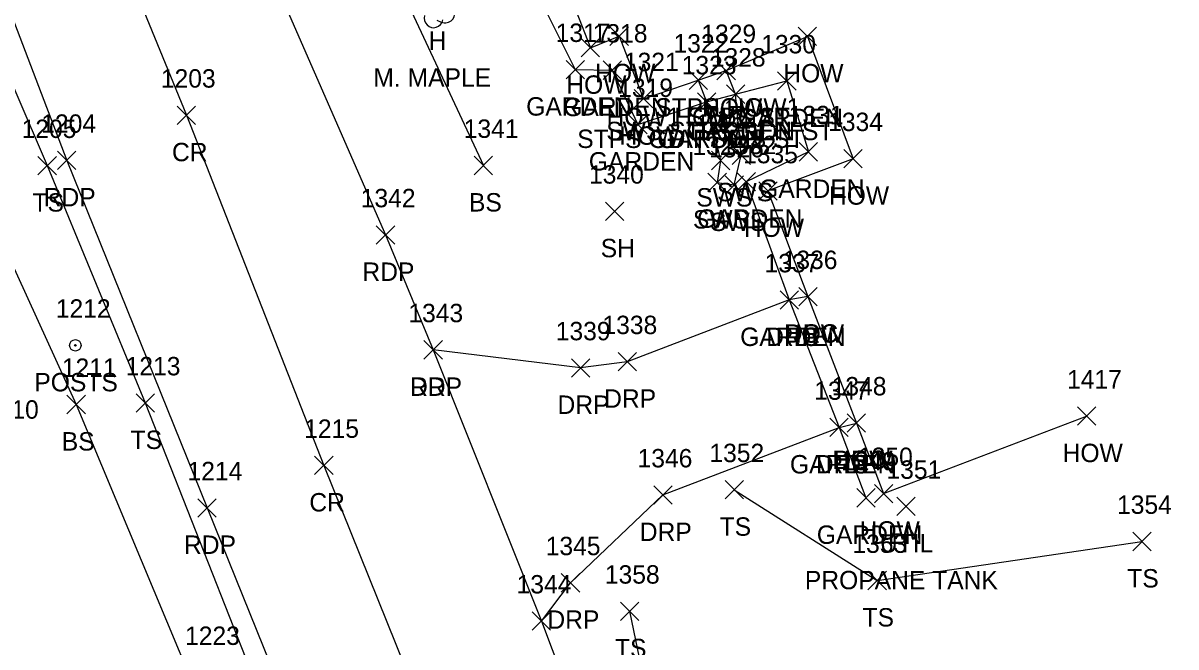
# Model space of a CAD drawing. Extents: x 1651305 to 1654558, y 539481 to 548441.
# Drawn here: x 1654203 to 1654328.2, y 544875.3 to 544943.1 of the extents above; entities that cross this region are included whole.
import ezdxf

# ---------------------------------------------------------------- set-up
doc = ezdxf.new("R2010")
doc.units = 0
for name, color, linetype in [('L_A', 7, 'Continuous'), ('L_C', 7, 'Continuous'), ('L_I', 7, 'Continuous'), ('L_TIC', 7, 'Continuous'), ('LAPB', 7, 'Continuous'), ('LBC', 7, 'Continuous'), ('LBF', 7, 'Continuous'), ('LELB', 7, 'Continuous'), ('LPST', 7, 'Continuous'), ('LTD', 7, 'Continuous'), ('P_A', 7, 'Continuous'), ('P_I', 7, 'Continuous'), ('P_TIC', 7, 'Continuous'), ('PET', 7, 'Continuous'), ('PRC', 7, 'Continuous'), ('R_A', 7, 'Continuous'), ('R_I', 7, 'Continuous'), ('R_TIC', 7, 'Continuous'), ('RDP', 7, 'Continuous'), ('RSW', 7, 'Continuous'), ('S_I', 7, 'Continuous'), ('U_A', 7, 'Continuous'), ('U_C', 7, 'Continuous'), ('U_I', 7, 'Continuous'), ('UDEFAULT', 7, 'Continuous')]:
    doc.layers.add(name, color=color, linetype=linetype)

msp = doc.modelspace()

# ---------------------------------------------------------------- linework, layer by layer
at = {"layer": 'L_TIC'}
for points in [[(1654266.72, 544940.66), (1654268.72, 544942.66)], [(1654268.72, 544940.66), (1654266.72, 544942.66)], [(1654287.15, 544940.64), (1654289.15, 544942.64)], [(1654289.15, 544940.64), (1654287.15, 544942.64)], [(1654263.6, 544939.4), (1654265.6, 544941.4)], [(1654265.6, 544939.4), (1654263.6, 544941.4)], [(1654261.96, 544937.03), (1654263.96, 544939.03)], [(1654263.96, 544937.03), (1654261.96, 544939.03)], [(1654265.98, 544936.97), (1654267.98, 544938.97)], [(1654267.98, 544936.97), (1654265.98, 544938.97)], [(1654278.34, 544936.92), (1654280.34, 544938.92)], [(1654280.34, 544936.92), (1654278.34, 544938.92)], [(1654278.34, 544936.92), (1654280.34, 544938.92)], [(1654280.34, 544936.92), (1654278.34, 544938.92)], [(1654275.31, 544935.88), (1654277.31, 544937.88)], [(1654277.31, 544935.88), (1654275.31, 544937.88)], [(1654275.31, 544935.88), (1654277.31, 544937.88)], [(1654277.31, 544935.88), (1654275.31, 544937.88)], [(1654284.92, 544935.79), (1654286.92, 544937.79)], [(1654286.92, 544935.79), (1654284.92, 544937.79)], [(1654279.36, 544934.36), (1654281.36, 544936.36)], [(1654281.36, 544934.36), (1654279.36, 544936.36)], [(1654279.36, 544934.36), (1654281.36, 544936.36)], [(1654281.36, 544934.36), (1654279.36, 544936.36)], [(1654269.37, 544933.86), (1654271.37, 544935.86)], [(1654271.37, 544933.86), (1654269.37, 544935.86)], [(1654276.21, 544933.51), (1654278.21, 544935.51)], [(1654278.21, 544933.51), (1654276.21, 544935.51)], [(1654276.21, 544933.51), (1654278.21, 544935.51)], [(1654278.21, 544933.51), (1654276.21, 544935.51)], [(1654268.76, 544931.06), (1654270.76, 544933.06)], [(1654270.76, 544931.06), (1654268.76, 544933.06)], [(1654287.26, 544928.09), (1654289.26, 544930.09)], [(1654289.26, 544928.09), (1654287.26, 544930.09)], [(1654204.63, 544926.6), (1654206.63, 544928.6)], [(1654206.63, 544926.6), (1654204.63, 544928.6)], [(1654251.98, 544926.61), (1654253.98, 544928.61)], [(1654253.98, 544926.61), (1654251.98, 544928.61)], [(1654292.11, 544927.35), (1654294.11, 544929.35)], [(1654294.11, 544927.35), (1654292.11, 544929.35)], [(1654280.51, 544924.84), (1654282.51, 544926.84)], [(1654282.51, 544924.84), (1654280.51, 544926.84)], [(1654282.87, 544923.85), (1654284.87, 544925.85)], [(1654284.87, 544923.85), (1654282.87, 544925.85)], [(1654266.23, 544921.64), (1654268.23, 544923.64)], [(1654268.23, 544921.64), (1654266.23, 544923.64)], [(1654285.19, 544912), (1654287.19, 544914)], [(1654287.19, 544912), (1654285.19, 544914)], [(1654287.22, 544912.36), (1654289.22, 544914.36)], [(1654289.22, 544912.36), (1654287.22, 544914.36)], [(1654207.78, 544900.64), (1654209.78, 544902.64)], [(1654209.78, 544900.64), (1654207.78, 544902.64)], [(1654215.28, 544900.81), (1654217.28, 544902.81)], [(1654217.28, 544900.81), (1654215.28, 544902.81)], [(1654317.47, 544899.38), (1654319.47, 544901.38)], [(1654319.47, 544899.38), (1654317.47, 544901.38)], [(1654290.59, 544898.15), (1654292.59, 544900.15)], [(1654292.59, 544898.15), (1654290.59, 544900.15)], [(1654292.48, 544898.63), (1654294.48, 544900.63)], [(1654294.48, 544898.63), (1654292.48, 544900.63)], [(1654279.22, 544891.38), (1654281.22, 544893.38)], [(1654281.22, 544891.38), (1654279.22, 544893.38)], [(1654293.51, 544890.5), (1654295.51, 544892.5)], [(1654295.51, 544890.5), (1654293.51, 544892.5)], [(1654295.43, 544890.96), (1654297.43, 544892.96)], [(1654297.43, 544890.96), (1654295.43, 544892.96)], [(1654323.47, 544885.76), (1654325.47, 544887.76)], [(1654325.47, 544885.76), (1654323.47, 544887.76)], [(1654294.73, 544881.52), (1654296.73, 544883.52)], [(1654296.73, 544881.52), (1654294.73, 544883.52)], [(1654267.86, 544878.18), (1654269.86, 544880.18)], [(1654269.86, 544878.18), (1654267.86, 544880.18)]]:
    msp.add_lwpolyline(points, dxfattribs=at)
at = {"layer": 'LAPB'}
for points in [[(1654256.41, 544951.2), (1654262.96, 544938.03), (1654266.98, 544937.97), (1654269.76, 544932.06), (1654277.21, 544934.51)], [(1654280.36, 544935.36), (1654285.92, 544936.79), (1654288.26, 544929.09), (1654281.51, 544925.84), (1654286.19, 544913)], [(1654291.59, 544899.15), (1654294.51, 544891.5)]]:
    msp.add_lwpolyline(points, dxfattribs=at)
at = {"layer": 'LBC'}
msp.add_lwpolyline([(1654281.63, 544981.34), (1654252.91, 544971.12), (1654257.65, 544958.01), (1654259.95, 544952.38), (1654264.6, 544940.4), (1654267.72, 544941.66), (1654270.37, 544934.86), (1654276.31, 544936.88), (1654279.34, 544937.92), (1654288.15, 544941.64), (1654293.11, 544928.35), (1654283.87, 544924.85), (1654288.22, 544913.36), (1654293.48, 544899.63), (1654296.43, 544891.96), (1654318.47, 544900.38)], dxfattribs=at)
at = {"layer": 'LBF'}
msp.add_lwpolyline([(1654276.31, 544936.88), (1654277.21, 544934.51), (1654280.36, 544935.36), (1654279.34, 544937.92)], dxfattribs=at)
at = {"layer": 'LELB'}
for points in [[(1654179.72, 544986.88), (1654191.76, 544959.88), (1654205.63, 544927.6), (1654216.28, 544901.81), (1654236.78, 544849.69), (1654250.25, 544817.94), (1654269.19, 544772.35), (1654285.71, 544732), (1654294.18, 544708.03), (1654311.84, 544664.34)], [(1654177.71, 544985.41), (1654186.4, 544960.29), (1654198.08, 544925.07), (1654208.78, 544901.64), (1654231.34, 544847.61), (1654245.85, 544816.46), (1654261.74, 544769.7), (1654274.87, 544730.83), (1654284.44, 544695.19), (1654297.61, 544656.98), (1654309.41, 544642.27)], [(1654232.47, 544981.12), (1654243.09, 544948.86), (1654252.98, 544927.61)], [(1654280.22, 544892.38), (1654295.73, 544882.52), (1654324.47, 544886.76)], [(1654268.86, 544879.18), (1654276.49, 544842.28), (1654286.12, 544815.62), (1654299.15, 544783.59), (1654310.71, 544759.79), (1654316.89, 544741.3), (1654328.16, 544712.61)]]:
    msp.add_lwpolyline(points, dxfattribs=at)
at = {"layer": 'LPST'}
for radius in [0.625, 0.0833]:
    msp.add_circle((1654208.69, 544908.07), radius, dxfattribs=at)
at = {"layer": 'LTD'}
for centre, major_axis, ratio in [((1654248.6, 544944.33), (-1.09, 0.79), 0.841452), ((1654247.6, 544943.67), (0.26, 1.06), 0.942809)]:
    msp.add_ellipse(centre, major_axis=major_axis, ratio=ratio, start_param=1.570796, end_param=4.712389, dxfattribs=at)
at = {"layer": 'P_TIC'}
for points in [[(1654219.75, 544932.07), (1654221.75, 544934.07)], [(1654221.75, 544932.07), (1654219.75, 544934.07)], [(1654206.76, 544927.16), (1654208.76, 544929.16)], [(1654208.76, 544927.16), (1654206.76, 544929.16)], [(1654241.36, 544919.07), (1654243.36, 544921.07)], [(1654243.36, 544919.07), (1654241.36, 544921.07)], [(1654246.53, 544906.58), (1654248.53, 544908.58)], [(1654248.53, 544906.58), (1654246.53, 544908.58)], [(1654234.66, 544894.02), (1654236.66, 544896.02)], [(1654236.66, 544894.02), (1654234.66, 544896.02)], [(1654221.99, 544889.41), (1654223.99, 544891.41)], [(1654223.99, 544889.41), (1654221.99, 544891.41)], [(1654258.28, 544877.11), (1654260.28, 544879.11)], [(1654260.28, 544877.11), (1654258.28, 544879.11)]]:
    msp.add_lwpolyline(points, dxfattribs=at)
at = {"layer": 'PET'}
for points in [[(1654139.13, 545176.5), (1654150.39, 545147.19), (1654157.16, 545131.71), (1654170.76, 545099.13), (1654178.15, 545080.65), (1654186.44, 545060.96), (1654201.83, 545022.37), (1654207.18, 545004.72), (1654219.14, 544973.24), (1654242.36, 544920.07), (1654247.53, 544907.58), (1654259.28, 544878.11), (1654268.46, 544853.76), (1654271.52, 544840.23), (1654282.76, 544813.43), (1654295.45, 544782.26), (1654306.75, 544753.72), (1654320.35, 544717.46), (1654325.71, 544702.64)], [(1654112.87, 545166.54), (1654122.04, 545140.21), (1654132.62, 545111.94), (1654135.36, 545108.19), (1654138.44, 545103.48), (1654151.39, 545069.68), (1654150.58, 545065.43), (1654160.56, 545041.12), (1654174.1, 545006.91), (1654181.29, 544989.93), (1654184.89, 544987.01), (1654195.03, 544961.54), (1654207.76, 544928.16), (1654222.99, 544890.41), (1654239.03, 544850.69), (1654252.07, 544818.68), (1654270.72, 544773.03), (1654287.36, 544732.43), (1654297.76, 544708.46), (1654313.88, 544667.1), (1654319.77, 544684.6), (1654325.71, 544702.64)]]:
    msp.add_lwpolyline(points, dxfattribs=at)
at = {"layer": 'PRC'}
msp.add_lwpolyline([(1654126.32, 545171.74), (1654141.33, 545133.41), (1654151.93, 545107.49), (1654165.21, 545072.69), (1654175.57, 545046.61), (1654188.97, 545011.94), (1654198.02, 544989.46), (1654207.45, 544965.61), (1654220.75, 544933.07), (1654235.66, 544895.02), (1654251.31, 544856.19), (1654265.06, 544822.16), (1654283.02, 544778.21), (1654298.76, 544737.49), (1654308.6, 544712.81), (1654319.77, 544684.6)], dxfattribs=at)
at = {"layer": 'R_TIC'}
for points in [[(1654279.36, 544934.36), (1654281.36, 544936.36)], [(1654281.36, 544934.36), (1654279.36, 544936.36)], [(1654276.21, 544933.51), (1654278.21, 544935.51)], [(1654278.21, 544933.51), (1654276.21, 544935.51)], [(1654277.73, 544927.15), (1654279.73, 544929.15)], [(1654279.73, 544927.15), (1654277.73, 544929.15)], [(1654279.98, 544927.72), (1654281.98, 544929.72)], [(1654281.98, 544927.72), (1654279.98, 544929.72)], [(1654277.36, 544924.76), (1654279.36, 544926.76)], [(1654279.36, 544924.76), (1654277.36, 544926.76)], [(1654279.22, 544924.49), (1654281.22, 544926.49)], [(1654281.22, 544924.49), (1654279.22, 544926.49)], [(1654285.19, 544912), (1654287.19, 544914)], [(1654287.19, 544912), (1654285.19, 544914)], [(1654285.19, 544912), (1654287.19, 544914)], [(1654287.19, 544912), (1654285.19, 544914)], [(1654287.22, 544912.36), (1654289.22, 544914.36)], [(1654289.22, 544912.36), (1654287.22, 544914.36)], [(1654246.53, 544906.58), (1654248.53, 544908.58)], [(1654248.53, 544906.58), (1654246.53, 544908.58)], [(1654267.6, 544905.29), (1654269.6, 544907.29)], [(1654269.6, 544905.29), (1654267.6, 544907.29)], [(1654262.54, 544904.62), (1654264.54, 544906.62)], [(1654264.54, 544904.62), (1654262.54, 544906.62)], [(1654290.59, 544898.15), (1654292.59, 544900.15)], [(1654292.59, 544898.15), (1654290.59, 544900.15)], [(1654290.59, 544898.15), (1654292.59, 544900.15)], [(1654292.59, 544898.15), (1654290.59, 544900.15)], [(1654292.48, 544898.63), (1654294.48, 544900.63)], [(1654294.48, 544898.63), (1654292.48, 544900.63)], [(1654271.47, 544890.81), (1654273.47, 544892.81)], [(1654273.47, 544890.81), (1654271.47, 544892.81)], [(1654261.44, 544881.27), (1654263.44, 544883.27)], [(1654263.44, 544881.27), (1654261.44, 544883.27)], [(1654258.28, 544877.11), (1654260.28, 544879.11)], [(1654260.28, 544877.11), (1654258.28, 544879.11)]]:
    msp.add_lwpolyline(points, dxfattribs=at)
at = {"layer": 'RDP'}
for points in [[(1654286.19, 544913), (1654268.6, 544906.29), (1654263.54, 544905.62), (1654247.53, 544907.58)], [(1654288.22, 544913.36), (1654286.19, 544913), (1654291.59, 544899.15), (1654293.48, 544899.63)], [(1654259.28, 544878.11), (1654262.44, 544882.27), (1654272.47, 544891.81), (1654291.59, 544899.15)]]:
    msp.add_lwpolyline(points, dxfattribs=at)
at = {"layer": 'RSW'}
msp.add_lwpolyline([(1654277.21, 544934.51), (1654278.73, 544928.15), (1654278.36, 544925.76), (1654280.22, 544925.49), (1654280.98, 544928.72), (1654280.36, 544935.36)], dxfattribs=at)
at = {"layer": 'UDEFAULT'}
for points in [[(1654297.87, 544889.57), (1654299.87, 544891.57)], [(1654299.87, 544889.57), (1654297.87, 544891.57)]]:
    msp.add_lwpolyline(points, dxfattribs=at)

# ---------------------------------------------------------------- texts
at = {"layer": 'L_A'}
for s, p in [('H', (1654247.03, 544940.17)), ('HOW', (1654265.11, 544936.66)), ('HOW', (1654285.54, 544936.64)), ('HOW', (1654261.98, 544935.4)), ('GARDEN', (1654257.63, 544933.03)), ('GARDEN', (1654261.65, 544932.97)), ('STPS HOW1', (1654271.64, 544932.92)), ('HOW', (1654276.73, 544932.92)), ('HOW1 STPS ST', (1654266.35, 544931.88)), ('HOW', (1654273.7, 544931.88)), ('GARDEN', (1654280.59, 544931.79)), ('SWS STPS GDN ST', (1654266.32, 544930.36)), ('GARDEN', (1654275.03, 544930.36)), ('STPS GDN SWS ST', (1654263.17, 544929.51)), ('HOW', (1654267.75, 544929.86)), ('GARDEN', (1654271.87, 544929.51)), ('GARDEN', (1654264.43, 544927.06)), ('GARDEN', (1654282.92, 544924.09)), ('HOW', (1654290.49, 544923.35)), ('TS', (1654204.04, 544922.6)), ('BS', (1654251.42, 544922.61)), ('GARDEN', (1654276.18, 544920.84)), ('HOW', (1654281.26, 544919.85)), ('SH', (1654265.72, 544917.64)), ('GARDEN', (1654280.86, 544908)), ('HOW', (1654285.6, 544908.36)), ('POSTS', (1654204.24, 544903.07)), ('BS', (1654207.22, 544896.64)), ('TS', (1654214.69, 544896.81)), ('HOW', (1654315.86, 544895.38)), ('GARDEN', (1654286.26, 544894.15)), ('HOW', (1654290.87, 544894.63)), ('TS', (1654278.63, 544887.38)), ('GARDEN', (1654289.18, 544886.5)), ('HOW', (1654293.82, 544886.96)), ('TS', (1654322.88, 544881.76)), ('TS', (1654294.14, 544877.52)), ('TS', (1654267.27, 544874.18))]:
    msp.add_text(s, height=2, dxfattribs=at).set_placement(p)
at = {"layer": 'L_C'}
msp.add_text('M. MAPLE', height=2, dxfattribs=at).set_placement((1654241.04, 544936.17))
at = {"layer": 'L_I'}
for s, p in [('1317', (1654260.83, 544941.03)), ('1318', (1654264.85, 544940.97)), ('1329', (1654276.64, 544940.92)), ('1329', (1654276.64, 544940.92)), ('1322', (1654273.62, 544939.88)), ('1322', (1654273.62, 544939.88)), ('1330', (1654283.14, 544939.79)), ('1321', (1654268.24, 544937.86)), ('1328', (1654277.67, 544938.36)), ('1328', (1654277.67, 544938.36)), ('1323', (1654274.51, 544937.51)), ('1323', (1654274.51, 544937.51)), ('1319', (1654267.62, 544935.06)), ('1331', (1654286.13, 544932.09)), ('1205', (1654202.86, 544930.6)), ('1341', (1654250.85, 544930.61)), ('1334', (1654290.41, 544931.35)), ('1332', (1654278.82, 544928.84)), ('1335', (1654281.18, 544927.85)), ('1340', (1654264.45, 544925.64)), ('1337', (1654283.5, 544916)), ('1336', (1654285.47, 544916.36)), ('1212', (1654206.57, 544911.07)), ('1211', (1654207.22, 544904.64)), ('1213', (1654214.15, 544904.81)), ('1417', (1654316.34, 544903.38)), ('1347', (1654288.9, 544902.15)), ('1348', (1654290.79, 544902.63)), ('1210', (1654198.77, 544900.1)), ('1352', (1654277.52, 544895.38)), ('1349', (1654291.81, 544894.5)), ('1350', (1654293.65, 544894.96)), ('1354', (1654321.77, 544889.76)), ('1353', (1654293.04, 544885.52)), ('1358', (1654266.17, 544882.18))]:
    msp.add_text(s, height=2, dxfattribs=at).set_placement(p)
at = {"layer": 'P_A'}
for s, p in [('CR', (1654219.18, 544928.07)), ('RDP', (1654205.25, 544923.16)), ('RDP', (1654239.85, 544915.07)), ('RDP', (1654245.02, 544902.58)), ('CR', (1654234.09, 544890.02)), ('RDP', (1654220.48, 544885.41))]:
    msp.add_text(s, height=2, dxfattribs=at).set_placement(p)
at = {"layer": 'P_I'}
for s, p in [('1203', (1654217.97, 544936.07)), ('1204', (1654204.99, 544931.16)), ('1342', (1654239.67, 544923.07)), ('1343', (1654244.84, 544910.58)), ('1215', (1654233.53, 544898.02)), ('1214', (1654220.87, 544893.41)), ('1344', (1654256.59, 544881.11))]:
    msp.add_text(s, height=2, dxfattribs=at).set_placement(p)
at = {"layer": 'R_A'}
for s, p in [('SWS STPS GDN ST', (1654266.32, 544930.36)), ('STPS GDN SWS ST', (1654263.17, 544929.51)), ('SWS', (1654276.1, 544923.15)), ('SWS', (1654278.35, 544923.72)), ('SWS', (1654275.73, 544920.76)), ('SWS', (1654277.59, 544920.49)), ('DRC', (1654283.68, 544908)), ('DRP', (1654283.68, 544908)), ('DRC', (1654285.7, 544908.36)), ('DRP', (1654245.02, 544902.58)), ('DRP', (1654261.03, 544900.62)), ('DRP', (1654266.09, 544901.29)), ('DRC', (1654289.08, 544894.15)), ('DRP', (1654289.08, 544894.15)), ('DRC', (1654290.97, 544894.63)), ('DRP', (1654269.96, 544886.81)), ('DRP', (1654259.93, 544877.27))]:
    msp.add_text(s, height=2, dxfattribs=at).set_placement(p)
at = {"layer": 'R_I'}
for s, p in [('1328', (1654277.67, 544938.36)), ('1323', (1654274.51, 544937.51)), ('1327', (1654278.29, 544931.72)), ('1324', (1654276.04, 544931.15)), ('1325', (1654275.67, 544928.76)), ('1326', (1654277.48, 544928.49)), ('1337', (1654283.5, 544916)), ('1337', (1654283.5, 544916)), ('1336', (1654285.47, 544916.36)), ('1343', (1654244.84, 544910.58)), ('1338', (1654265.91, 544909.29)), ('1339', (1654260.84, 544908.62)), ('1347', (1654288.9, 544902.15)), ('1347', (1654288.9, 544902.15)), ('1348', (1654290.79, 544902.63)), ('1346', (1654269.72, 544894.81)), ('1345', (1654259.75, 544885.27)), ('1344', (1654256.59, 544881.11))]:
    msp.add_text(s, height=2, dxfattribs=at).set_placement(p)
at = {"layer": 'S_I'}
msp.add_text('1223', height=2, dxfattribs=at).set_placement((1654220.6, 544875.52))
at = {"layer": 'U_A'}
msp.add_text('UTIL', height=2, dxfattribs=at).set_placement((1654296.03, 544885.57))
at = {"layer": 'U_C'}
msp.add_text('PROPANE TANK', height=2, dxfattribs=at).set_placement((1654287.88, 544881.57))
at = {"layer": 'U_I'}
msp.add_text('1351', height=2, dxfattribs=at).set_placement((1654296.74, 544893.57))

doc.saveas('drawing.dxf')
